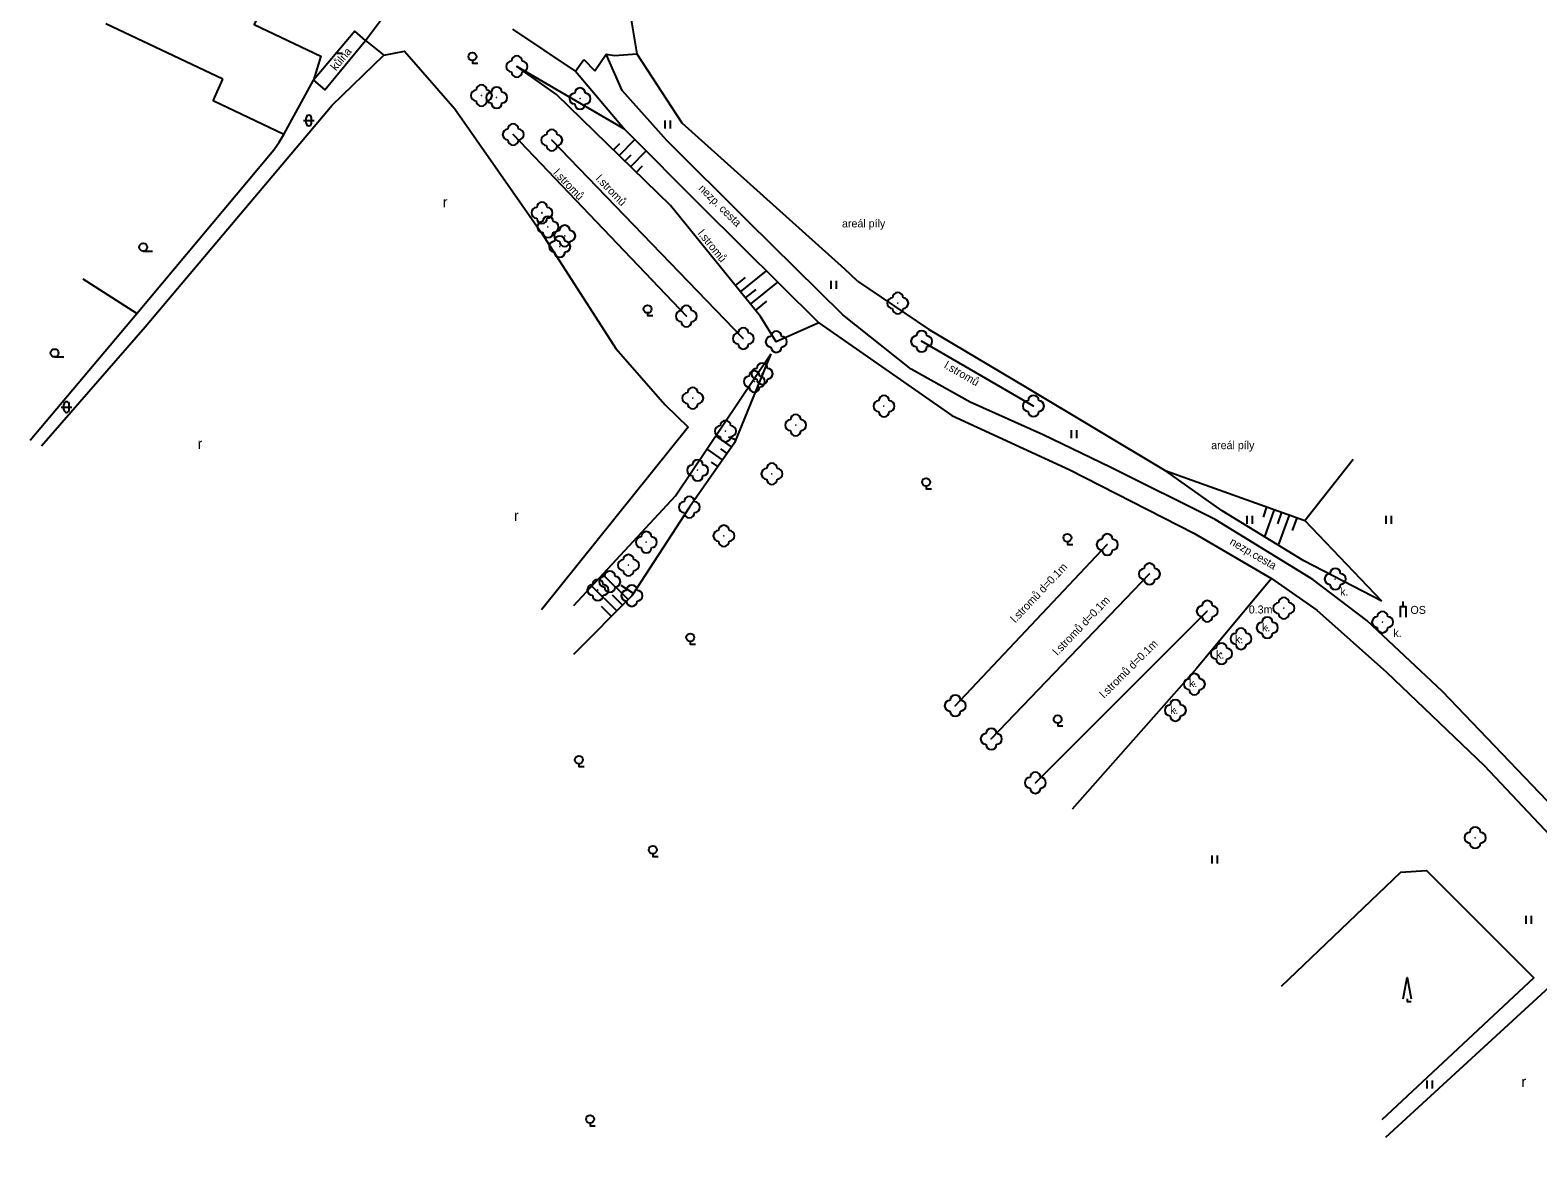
# Model space of a CAD drawing. Extents: x -544674 to -541478, y -1199076 to -1195527.
# Drawn here: x -543612 to -543470.1, y -1197036.9 to -1196931.8 of the extents above; entities that cross this region are included whole.
import ezdxf

# ---------------------------------------------------------------- set-up
doc = ezdxf.new("R2010")
doc.units = 0
for name, color, linetype in [('BUDOVY_MĚŘ', 7, 'Continuous'), ('BUDOVY_NEMĚŘ', 7, 'Continuous'), ('POMOC_POPIS', 7, 'Continuous'), ('ROZHRANÍ_PLOCH', 7, 'Continuous'), ('VÝŠKOPIS', 7, 'Continuous'), ('ZELEŇ', 7, 'Continuous'), ('ZN_BUDOV', 7, 'Continuous'), ('ZN_DOPLŇKOVÉ', 7, 'Continuous'), ('ZN_KULTUR', 7, 'Continuous')]:
    doc.layers.add(name, color=color, linetype=linetype)

msp = doc.modelspace()

# ---------------------------------------------------------------- linework, layer by layer
at = {"layer": 'BUDOVY_MĚŘ'}
for points in [[(-543594.06, -1196922.2), (-543587.93, -1196925.02), (-543590.93, -1196931.25), (-543584.67, -1196934.23), (-543585.35, -1196936.49)], [(-543585.35, -1196936.49), (-543584.28, -1196937.39), (-543580.45, -1196932.76), (-543581.48, -1196931.89), (-543585.35, -1196936.49)], [(-543588.15, -1196941.62), (-543585.35, -1196936.49)]]:
    msp.add_lwpolyline(points, dxfattribs=at)
at = {"layer": 'BUDOVY_NEMĚŘ'}
for points in [[(-543593.88, -1196936.4), (-543604.91, -1196931.19)], [(-543594.81, -1196938.44), (-543593.88, -1196936.4)], [(-543588.15, -1196941.62), (-543594.81, -1196938.44)]]:
    msp.add_lwpolyline(points, dxfattribs=at)
at = {"layer": 'ROZHRANÍ_PLOCH'}
for points in [[(-543580.45, -1196932.76), (-543578.3, -1196929.87)], [(-543560.69, -1196935.66), (-543566.61, -1196931.69)], [(-543558.87, -1196935.61), (-543557.81, -1196934.05)], [(-543365.56, -1197143.9), (-543382.51, -1197120.5), (-543395.18, -1197102.8), (-543416.84, -1197070.78), (-543427.94, -1197054.5), (-543446.57, -1197029.47), (-543464.32, -1197009.47), (-543479.1, -1196994.03), (-543486.22, -1196987.35), (-543491.29, -1196983.49), (-543500.47, -1196977.85), (-543510.37, -1196972.9), (-543516.66, -1196969.88), (-543523.55, -1196966.79), (-543529.1, -1196963.69), (-543535.54, -1196958.59), (-543544.49, -1196949.75), (-543552.11, -1196942.17), (-543556.31, -1196937.46), (-543557.81, -1196934.05)], [(-543557.81, -1196934.05), (-543557.02, -1196934.18)], [(-543557.02, -1196934.18), (-543554.93, -1196934.03)], [(-543560.69, -1196935.66), (-543559.91, -1196934.56)], [(-543560.69, -1196935.66), (-543556.07, -1196941.11), (-543548.81, -1196948.41), (-543537.8, -1196959.32), (-543525.28, -1196968.06), (-543514.16, -1196973.16), (-543502.5, -1196979.12), (-543495.19, -1196983.4), (-543490.92, -1196986.38), (-543484.37, -1196992.19), (-543475.15, -1197000.99), (-543461.74, -1197015.22)], [(-543559.91, -1196934.56), (-543558.87, -1196935.61)]]:
    msp.add_lwpolyline(points, dxfattribs=at)
at = {"layer": 'VÝŠKOPIS'}
for points in [[(-543556.07, -1196941.11), (-543566.22, -1196935.21)], [(-543557.11, -1196943.06), (-543556.52, -1196942.46)], [(-543556.58, -1196943.59), (-543555.11, -1196942.08)], [(-543556.04, -1196944.11), (-543555.45, -1196943.51)], [(-543555.5, -1196944.63), (-543554.05, -1196943.14)], [(-543554.97, -1196945.16), (-543554.39, -1196944.57)], [(-543545.65, -1196955.83), (-543544.69, -1196955.06)], [(-543545.17, -1196956.41), (-543542.73, -1196954.43)], [(-543544.23, -1196957.57), (-543541.66, -1196955.49)], [(-543544.7, -1196956.99), (-543543.7, -1196956.18)], [(-543543.76, -1196958.16), (-543542.7, -1196957.3)], [(-543537.8, -1196959.32), (-543541.8, -1196961.11)], [(-543542.3, -1196962.24), (-543545.74, -1196970.62), (-543549.98, -1196976.68), (-543555.39, -1196985.01), (-543560.87, -1196990.55)], [(-543560.85, -1196985.92), (-543551.29, -1196975.61), (-543542.3, -1196962.24)], [(-543546.87, -1196972.23), (-543548.33, -1196971.2)], [(-543546.01, -1196971), (-543547.49, -1196969.96)], [(-543546.44, -1196971.61), (-543547.02, -1196971.2)], [(-543545.63, -1196970.35), (-543546.3, -1196970.08)], [(-543547.29, -1196972.84), (-543547.88, -1196972.44)], [(-543484.81, -1196985.52), (-543492.14, -1196981.73), (-543499.84, -1196977.01), (-543505.2, -1196973.22)], [(-543495.64, -1196976.66), (-543495.98, -1196977.62)], [(-543494.93, -1196976.91), (-543495.85, -1196979.46)], [(-543494.23, -1196977.16), (-543494.61, -1196978.24)], [(-543493.52, -1196977.42), (-543494.54, -1196980.26)], [(-543492.81, -1196977.67), (-543493.24, -1196978.86)], [(-543484.81, -1196985.52), (-543492.06, -1196977.94)], [(-543555.74, -1196985.37), (-543558.14, -1196982.99)], [(-543556.8, -1196986.43), (-543559.16, -1196984.1)], [(-543556.27, -1196985.9), (-543557.22, -1196984.96)], [(-543555.25, -1196984.8), (-543556.39, -1196984.06)], [(-543557.32, -1196986.96), (-543558.26, -1196986.04)]]:
    msp.add_lwpolyline(points, dxfattribs=at)
at = {"layer": 'ZELEŇ'}
for points in [[(-543580.45, -1196932.76), (-543578.73, -1196934.13)], [(-543610.96, -1196970.9), (-543601.19, -1196959.7), (-543583.61, -1196938.85), (-543578.73, -1196934.13), (-543576.78, -1196933.78), (-543572.04, -1196939.19), (-543563.89, -1196950.86), (-543556.89, -1196961.74), (-543552.26, -1196967.06), (-543550.09, -1196969.16), (-543563.89, -1196986.34)], [(-543541.8, -1196961.11), (-543543.29, -1196958.73), (-543551.76, -1196948.29), (-543562.47, -1196937.83), (-543566.22, -1196935.21)], [(-543566.56, -1196941.61), (-543550.26, -1196958.7)], [(-543544.9, -1196960.8), (-543562.93, -1196942.14)], [(-543517.59, -1196967.16), (-543528.12, -1196961.07)], [(-543524.95, -1196995.36), (-543510.64, -1196980.2)], [(-543521.56, -1196998.49), (-543506.67, -1196982.96)], [(-543495.19, -1196983.4), (-543502.22, -1196991.84), (-543513.95, -1197005.09)], [(-543517.41, -1197002.61), (-543501.23, -1196986.47)], [(-543494.25, -1197021.74), (-543483.01, -1197011.03), (-543480.6, -1197010.86), (-543470.49, -1197020.96), (-543484.79, -1197034.32)], [(-543461.74, -1197015.22), (-543469.06, -1197021.86), (-543484.45, -1197035.99)]]:
    msp.add_lwpolyline(points, dxfattribs=at)
for centre in [(-543566.22, -1196935.21), (-543569.55, -1196937.94), (-543568.12, -1196938.14), (-543560.27, -1196938.23), (-543566.56, -1196941.61), (-543562.93, -1196942.14), (-543563.85, -1196948.98), (-543563.29, -1196950.31), (-543561.71, -1196951.15), (-543562.18, -1196952.16), (-543530.36, -1196957.48), (-543550.26, -1196958.7), (-543544.9, -1196960.8), (-543541.8, -1196961.11), (-543528.12, -1196961.07), (-543543.13, -1196964.12), (-543543.86, -1196964.86), (-543549.66, -1196966.42), (-543531.66, -1196967.17), (-543517.59, -1196967.16), (-543546.58, -1196969.52), (-543539.97, -1196968.96), (-543549.2, -1196973.21), (-543542.21, -1196973.54), (-543549.98, -1196976.68), (-543546.73, -1196979.38), (-543554.03, -1196979.98), (-543510.64, -1196980.2), (-543555.71, -1196982.14), (-543557.47, -1196983.69), (-543506.67, -1196982.96), (-543489.18, -1196983.44), (-543558.59, -1196984.47), (-543555.39, -1196985.01), (-543501.23, -1196986.47), (-543494.02, -1196986.18), (-543495.58, -1196988.02), (-543484.73, -1196987.49), (-543498.05, -1196989.06), (-543499.89, -1196990.46), (-543502.44, -1196993.34), (-543524.95, -1196995.36), (-543504.23, -1196995.8), (-543521.56, -1196998.49), (-543517.41, -1197002.61), (-543476.01, -1197007.78)]:
    msp.add_circle(centre, 0.0005, dxfattribs=at)
for centre, start, end in [((-543566.22, -1196934.71), 0, 179.99999), ((-543566.72, -1196935.21), 89.99999, 269.99999), ((-543566.22, -1196935.71), 179.99999, 359.99999), ((-543565.72, -1196935.21), 270, 89.99999), ((-543569.55, -1196937.44), 0, 179.99999), ((-543568.12, -1196937.64), 0, 179.99999), ((-543570.05, -1196937.94), 89.99999, 269.99999), ((-543569.55, -1196938.44), 179.99999, 359.99999), ((-543568.62, -1196938.14), 89.99999, 269.99999), ((-543569.05, -1196937.94), 270, 89.99999), ((-543567.62, -1196938.14), 270, 89.99999), ((-543560.77, -1196938.23), 89.99999, 269.99999), ((-543560.27, -1196937.73), 0, 179.99999), ((-543559.77, -1196938.23), 270, 89.99999), ((-543568.12, -1196938.64), 179.99999, 359.99999), ((-543560.27, -1196938.73), 179.99999, 359.99999), ((-543567.06, -1196941.61), 89.99999, 269.99999), ((-543566.56, -1196941.11), 0, 179.99999), ((-543566.06, -1196941.61), 270, 89.99999), ((-543562.93, -1196941.64), 0, 179.99999), ((-543566.56, -1196942.11), 179.99999, 359.99999), ((-543563.43, -1196942.14), 89.99999, 269.99999), ((-543562.93, -1196942.64), 179.99999, 359.99999), ((-543562.43, -1196942.14), 270, 89.99999), ((-543564.35, -1196948.98), 89.99999, 269.99999), ((-543563.85, -1196948.48), 0, 179.99999), ((-543563.35, -1196948.98), 270, 89.99999), ((-543563.85, -1196949.48), 179.99999, 359.99999), ((-543563.79, -1196950.31), 89.99999, 269.99999), ((-543563.29, -1196949.81), 0, 179.99999), ((-543562.79, -1196950.31), 270, 89.99999), ((-543563.29, -1196950.81), 179.99999, 359.99999), ((-543562.21, -1196951.15), 89.99999, 269.99999), ((-543562.18, -1196951.66), 0, 179.99999), ((-543561.71, -1196950.65), 0, 179.99999), ((-543561.21, -1196951.15), 270, 89.99999), ((-543562.68, -1196952.16), 89.99999, 269.99999), ((-543562.18, -1196952.66), 179.99999, 359.99999), ((-543561.71, -1196951.65), 179.99999, 359.99999), ((-543561.68, -1196952.16), 270, 89.99999), ((-543530.86, -1196957.48), 89.99999, 269.99999), ((-543530.36, -1196956.98), 0, 179.99999), ((-543529.86, -1196957.48), 270, 89.99999), ((-543550.76, -1196958.7), 89.99999, 269.99999), ((-543550.26, -1196958.2), 0, 179.99999), ((-543549.76, -1196958.7), 270, 89.99999), ((-543530.36, -1196957.98), 179.99999, 359.99999), ((-543550.26, -1196959.2), 179.99999, 359.99999), ((-543544.9, -1196960.3), 0, 179.99999), ((-543545.4, -1196960.8), 89.99999, 269.99999), ((-543544.4, -1196960.8), 270, 89.99999), ((-543542.3, -1196961.11), 89.99999, 269.99999), ((-543541.8, -1196960.61), 0, 179.99999), ((-543541.3, -1196961.11), 270, 89.99999), ((-543528.62, -1196961.07), 89.99999, 269.99999), ((-543528.12, -1196960.57), 0, 179.99999), ((-543527.62, -1196961.07), 270, 89.99999), ((-543544.9, -1196961.3), 179.99999, 359.99999), ((-543541.8, -1196961.61), 179.99999, 359.99999), ((-543528.12, -1196961.57), 179.99999, 359.99999), ((-543543.86, -1196964.36), 0, 179.99999), ((-543543.63, -1196964.12), 89.99999, 269.99999), ((-543543.13, -1196963.62), 0, 179.99999), ((-543542.63, -1196964.12), 270, 89.99999), ((-543549.66, -1196965.92), 0, 179.99999), ((-543544.36, -1196964.86), 89.99999, 269.99999), ((-543543.86, -1196965.36), 179.99999, 359.99999), ((-543543.13, -1196964.62), 179.99999, 359.99999), ((-543543.36, -1196964.86), 270, 89.99999), ((-543550.16, -1196966.42), 89.99999, 269.99999), ((-543549.66, -1196966.92), 179.99999, 359.99999), ((-543549.16, -1196966.42), 270, 89.99999), ((-543532.16, -1196967.17), 89.99999, 269.99999), ((-543531.66, -1196966.67), 0, 179.99999), ((-543531.16, -1196967.17), 270, 89.99999), ((-543518.09, -1196967.16), 89.99999, 269.99999), ((-543517.59, -1196966.66), 0, 179.99999), ((-543517.09, -1196967.16), 270, 89.99999), ((-543539.97, -1196968.46), 0, 179.99999), ((-543531.66, -1196967.67), 179.99999, 359.99999), ((-543517.59, -1196967.66), 179.99999, 359.99999), ((-543547.08, -1196969.52), 89.99999, 269.99999), ((-543546.58, -1196969.02), 0, 179.99999), ((-543546.08, -1196969.52), 270, 89.99999), ((-543540.47, -1196968.96), 89.99999, 269.99999), ((-543539.97, -1196969.46), 179.99999, 359.99999), ((-543539.47, -1196968.96), 270, 89.99999), ((-543546.58, -1196970.02), 179.99999, 359.99999), ((-543549.2, -1196972.71), 0, 179.99999), ((-543542.21, -1196973.04), 0, 179.99999), ((-543549.7, -1196973.21), 89.99999, 269.99999), ((-543549.2, -1196973.71), 179.99999, 359.99999), ((-543548.7, -1196973.21), 270, 89.99999), ((-543542.71, -1196973.54), 89.99999, 269.99999), ((-543542.21, -1196974.04), 179.99999, 359.99999), ((-543541.71, -1196973.54), 270, 89.99999), ((-543550.48, -1196976.68), 89.99999, 269.99999), ((-543549.98, -1196976.18), 0, 179.99999), ((-543549.48, -1196976.68), 270, 89.99999), ((-543549.98, -1196977.18), 179.99999, 359.99999), ((-543554.53, -1196979.98), 89.99999, 269.99999), ((-543554.03, -1196979.48), 0, 179.99999), ((-543553.53, -1196979.98), 270, 89.99999), ((-543547.23, -1196979.38), 89.99999, 269.99999), ((-543546.73, -1196978.88), 0, 179.99999), ((-543546.23, -1196979.38), 270, 89.99999), ((-543511.14, -1196980.2), 89.99999, 269.99999), ((-543510.64, -1196979.7), 0, 179.99999), ((-543510.14, -1196980.2), 270, 89.99999), ((-543555.71, -1196981.64), 0, 179.99999), ((-543554.03, -1196980.48), 179.99999, 359.99999), ((-543546.73, -1196979.88), 179.99999, 359.99999), ((-543510.64, -1196980.7), 179.99999, 359.99999), ((-543556.21, -1196982.14), 89.99999, 269.99999), ((-543555.21, -1196982.14), 270, 89.99999), ((-543507.17, -1196982.96), 89.99999, 269.99999), ((-543506.67, -1196982.46), 0, 179.99999), ((-543506.17, -1196982.96), 270, 89.99999), ((-543489.18, -1196982.94), 0, 179.99999), ((-543559.09, -1196984.47), 89.99999, 269.99999), ((-543558.59, -1196983.97), 0, 179.99999), ((-543557.97, -1196983.69), 89.99999, 269.99999), ((-543558.09, -1196984.47), 270, 89.99999), ((-543557.47, -1196983.19), 0, 179.99999), ((-543556.97, -1196983.69), 270, 89.99999), ((-543555.71, -1196982.64), 179.99999, 359.99999), ((-543506.67, -1196983.46), 179.99999, 359.99999), ((-543489.68, -1196983.44), 89.99999, 269.99999), ((-543489.18, -1196983.94), 179.99999, 359.99999), ((-543488.68, -1196983.44), 270, 89.99999), ((-543558.59, -1196984.97), 179.99999, 359.99999), ((-543557.47, -1196984.19), 179.99999, 359.99999), ((-543555.89, -1196985.01), 89.99999, 269.99999), ((-543555.39, -1196984.51), 0, 179.99999), ((-543554.89, -1196985.01), 270, 89.99999), ((-543494.02, -1196985.68), 0, 179.99999), ((-543555.39, -1196985.51), 179.99999, 359.99999), ((-543501.73, -1196986.47), 89.99999, 269.99999), ((-543501.23, -1196985.97), 0, 179.99999), ((-543500.73, -1196986.47), 270, 89.99999), ((-543494.52, -1196986.18), 89.99999, 269.99999), ((-543494.02, -1196986.68), 179.99999, 359.99999), ((-543493.52, -1196986.18), 270, 89.99999), ((-543484.73, -1196986.99), 0, 179.99999), ((-543501.23, -1196986.97), 179.99999, 359.99999), ((-543498.05, -1196988.56), 0, 179.99999), ((-543496.08, -1196988.02), 89.99999, 269.99999), ((-543495.58, -1196987.52), 0, 179.99999), ((-543495.08, -1196988.02), 270, 89.99999), ((-543485.23, -1196987.49), 89.99999, 269.99999), ((-543484.73, -1196987.99), 179.99999, 359.99999), ((-543484.23, -1196987.49), 270, 89.99999), ((-543499.89, -1196989.96), 0, 179.99999), ((-543498.55, -1196989.06), 89.99999, 269.99999), ((-543498.05, -1196989.56), 179.99999, 359.99999), ((-543497.55, -1196989.06), 270, 89.99999), ((-543495.58, -1196988.52), 179.99999, 359.99999), ((-543500.39, -1196990.46), 89.99999, 269.99999), ((-543499.89, -1196990.96), 179.99999, 359.99999), ((-543499.39, -1196990.46), 270, 89.99999), ((-543502.44, -1196992.84), 0, 179.99999), ((-543502.94, -1196993.34), 89.99999, 269.99999), ((-543502.44, -1196993.84), 179.99999, 359.99999), ((-543501.94, -1196993.34), 270, 89.99999), ((-543525.45, -1196995.36), 89.99999, 269.99999), ((-543524.95, -1196994.86), 0, 179.99999), ((-543524.45, -1196995.36), 270, 89.99999), ((-543504.73, -1196995.8), 89.99999, 269.99999), ((-543504.23, -1196995.3), 0, 179.99999), ((-543503.73, -1196995.8), 270, 89.99999), ((-543524.95, -1196995.86), 179.99999, 359.99999), ((-543504.23, -1196996.3), 179.99999, 359.99999), ((-543522.06, -1196998.49), 89.99999, 269.99999), ((-543521.56, -1196997.99), 0, 179.99999), ((-543521.06, -1196998.49), 270, 89.99999), ((-543521.56, -1196998.99), 179.99999, 359.99999), ((-543517.91, -1197002.61), 89.99999, 269.99999), ((-543517.41, -1197002.11), 0, 179.99999), ((-543516.91, -1197002.61), 270, 89.99999), ((-543517.41, -1197003.11), 179.99999, 359.99999), ((-543476.51, -1197007.78), 89.99999, 269.99999), ((-543476.01, -1197007.28), 0, 179.99999), ((-543475.51, -1197007.78), 270, 89.99999), ((-543476.01, -1197008.28), 179.99999, 359.99999)]:
    msp.add_arc(centre, 0.5, start, end, dxfattribs=at)
at = {"layer": 'ZN_BUDOV'}
msp.add_line((-543583.12, -1196933.97), (-543582.62, -1196933.97), dxfattribs=at)
at = {"layer": 'ZN_DOPLŇKOVÉ'}
msp.add_line((-543482.8, -1196986.04), (-543482.8, -1196985.54), dxfattribs=at)
for points in [[(-543555.66, -1196929.7), (-543554.93, -1196934.03)], [(-543554.93, -1196934.03), (-543550.7, -1196940.52), (-543535.36, -1196954.25)], [(-543589.1, -1196943.06), (-543588.59, -1196942.33)], [(-543588.59, -1196942.33), (-543588.15, -1196941.62)], [(-543601.99, -1196958.44), (-543589.1, -1196943.06)], [(-543612.03, -1196970.36), (-543601.99, -1196958.44), (-543607.05, -1196955.23)], [(-543534.16, -1196955.4), (-543535.36, -1196954.25)], [(-543534.16, -1196955.4), (-543527.47, -1196959.94), (-543518.34, -1196965.35), (-543505.2, -1196973.22), (-543492.06, -1196977.94), (-543487.49, -1196972.16)], [(-543483.05, -1196987.04), (-543483.05, -1196986.04), (-543482.55, -1196986.04), (-543482.55, -1196987.04)]]:
    msp.add_lwpolyline(points, dxfattribs=at)
at = {"layer": 'ZN_KULTUR'}
for p, q in [((-543586.3, -1196940.29), (-543585.3, -1196940.29)), ((-543586.05, -1196940.54), (-543586.05, -1196940.04)), ((-543585.55, -1196940.54), (-543585.55, -1196940.04)), ((-543552.25, -1196941.045), (-543552.25, -1196940.295)), ((-543551.75, -1196941.045), (-543551.75, -1196940.295)), ((-543601.39, -1196952.585), (-543600.515, -1196952.585)), ((-543536.63, -1196956.125), (-543536.63, -1196955.375)), ((-543536.13, -1196956.125), (-543536.13, -1196955.375)), ((-543609.73, -1196962.545), (-543608.855, -1196962.545)), ((-543609.1, -1196967.26), (-543608.1, -1196967.26)), ((-543608.85, -1196967.51), (-543608.85, -1196967.01)), ((-543608.35, -1196967.51), (-543608.35, -1196967.01)), ((-543514.02, -1196970.175), (-543514.02, -1196969.425)), ((-543513.52, -1196970.175), (-543513.52, -1196969.425)), ((-543497.46, -1196978.235), (-543497.46, -1196977.485)), ((-543496.96, -1196978.235), (-543496.96, -1196977.485)), ((-543484.38, -1196978.235), (-543484.38, -1196977.485)), ((-543483.88, -1196978.235), (-543483.88, -1196977.485)), ((-543500.78, -1197010.215), (-543500.78, -1197009.465)), ((-543500.28, -1197010.215), (-543500.28, -1197009.465)), ((-543471.2, -1197015.885), (-543471.2, -1197015.135)), ((-543470.7, -1197015.885), (-543470.7, -1197015.135)), ((-543480.53, -1197031.375), (-543480.53, -1197030.625)), ((-543480.03, -1197031.375), (-543480.03, -1197030.625))]:
    msp.add_line(p, q, dxfattribs=at)
for points in [[(-543570.4, -1196934.655), (-543570.4, -1196934.905), (-543569.9, -1196934.905)], [(-543553.91, -1196958.405), (-543553.91, -1196958.655), (-543553.41, -1196958.655)], [(-543527.7, -1196974.695), (-543527.7, -1196974.945), (-543527.2, -1196974.945)], [(-543514.39, -1196979.925), (-543514.39, -1196980.175), (-543513.89, -1196980.175)], [(-543549.89, -1196989.305), (-543549.89, -1196989.555), (-543549.39, -1196989.555)], [(-543515.31, -1196997.015), (-543515.31, -1196997.265), (-543514.81, -1196997.265)], [(-543560.37, -1197000.825), (-543560.37, -1197001.075), (-543559.87, -1197001.075)], [(-543553.42, -1197009.295), (-543553.42, -1197009.545), (-543552.92, -1197009.545)], [(-543482.795, -1197022.93), (-543482.42, -1197020.93), (-543482.045, -1197022.93)], [(-543482.42, -1197022.93), (-543482.42, -1197023.18), (-543482.045, -1197023.18)], [(-543559.33, -1197034.635), (-543559.33, -1197034.885), (-543558.83, -1197034.885)]]:
    msp.add_lwpolyline(points, dxfattribs=at)
for centre in [(-543570.4, -1196934.28), (-543601.39, -1196952.21), (-543553.91, -1196958.03), (-543609.73, -1196962.17), (-543527.7, -1196974.32), (-543514.39, -1196979.55), (-543549.89, -1196988.93), (-543515.31, -1196996.64), (-543560.37, -1197000.45), (-543553.42, -1197008.92), (-543559.33, -1197034.26)]:
    msp.add_circle(centre, 0.375, dxfattribs=at)
for centre, start, end in [((-543585.8, -1196940.04), 0, 179.99999), ((-543585.8, -1196940.54), 179.99999, 359.99999), ((-543608.6, -1196967.01), 0, 179.99999), ((-543608.6, -1196967.51), 179.99999, 359.99999)]:
    msp.add_arc(centre, 0.25, start, end, dxfattribs=at)

# ---------------------------------------------------------------- texts
at = {"layer": 'POMOC_POPIS'}
for s, rotation, p in [('kůlna', 50.17693, (-543583.25, -1196935.66)), ('nezp. cesta', 315.26138, (-543549.17, -1196946.75)), ('nezp.cesta', 329.65106, (-543499.18, -1196980.13))]:
    msp.add_text(s, height=0.75, rotation=rotation, dxfattribs=at).set_placement(p)
for s, p in [('areál píly', (-543535.61, -1196950.35)), ('areál píly', (-543500.86, -1196971.22)), ('OS', (-543482.1, -1196986.72))]:
    msp.add_text(s, height=0.75, dxfattribs=at).set_placement(p)
at = {"layer": 'ZELEŇ'}
for s, rotation, p in [('l.stromů', 313.64465, (-543562.84, -1196945.28)), ('l.stromů', 314.01628, (-543558.85, -1196945.83)), ('l.stromů', 309.05251, (-543549.24, -1196950.94)), ('l.stromů', 329.95716, (-543526.06, -1196963.54)), ('l.stromů d=0.1m', 46.65212, (-543519.29, -1196987.61)), ('l.stromů d=0.1m', 46.20526, (-543515.32, -1196990.69)), ('l.stromů d=0.1m', 44.92909, (-543510.93, -1196994.7))]:
    msp.add_text(s, height=0.75, rotation=rotation, dxfattribs=at).set_placement(p)
for s, p in [('k.', (-543488.72, -1196985.01)), ('0.3m', (-543497.32, -1196986.68)), ('k.', (-543496.08, -1196988.36)), ('k.', (-543483.71, -1196988.89)), ('k.', (-543498.62, -1196989.48)), ('k.', (-543500.4, -1196990.92)), ('k.', (-543502.94, -1196993.61)), ('k.', (-543504.72, -1196996.14))]:
    msp.add_text(s, height=0.75, dxfattribs=at).set_placement(p)
at = {"layer": 'ZN_KULTUR'}
for p in [(-543573.188, -1196948.472), (-543596.268, -1196971.192), (-543566.488, -1196977.972), (-543471.658, -1197031.242)]:
    msp.add_text('r', height=1, dxfattribs=at).set_placement(p)

doc.saveas('drawing.dxf')
